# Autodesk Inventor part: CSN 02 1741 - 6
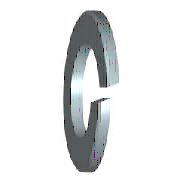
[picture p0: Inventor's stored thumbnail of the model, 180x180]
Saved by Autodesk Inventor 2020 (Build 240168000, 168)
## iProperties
Created: 2019-01
Part Number: CSN 02 1741 - 6
Material: Ocel, měkká
Description: Pružné podložky obdélníkového průřezu
Document SubType Name: Modeling
Standard: CSN 02 1741
Designer: doma
Standards Organization: CSN
Language: cs-CZ
Size Designation: 6
Categories: <MemberInstance><Categories><Category DisplayName="Spojovací materiál" InternalName="e4da775c-781d-43d5-af7c-5136215cf5a6" Mnemonic="FSTN"><Category DisplayName
Density: 7.85 g/cm^3
Appearance: Pololeštěná
IsCustomPart: 0
Author: doma
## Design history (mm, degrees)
sketch "Náčrt1"
  geometry: C1 r 5.55 at (0, 0); C2 r 3.05 at (0, 0); 1 further point
  constraints: 2 centre point, 2 coincident
  dimensions: "d0" = 6.1 diameter of C2 (= SD1); "d1" = 11.1 diameter of C1 (= SD2)
extrude "Těleso" new body sketch "Náčrt1" distance "d2" = 1.6 (= SD); taper "d3" = 0 deg
sketch "Náčrt2"
  geometry: L1 (0, -3.05)-(0, 3.05) reference; L2 (1.6, 5.55)-(1.6, -5.55) reference; L3 (-1.2, 0)-(7.2, 0) reference; L4 (0, -0.32)-(1.6, -0.038); L5 (0, 0.32)-(1.6, 0.602)
  constraints: 4 end point, 4 point on line, 1 parallel
  dimensions: "d4" = 0.32 distance from line of L3 L4.start (= 0.2 x SD); "d5" = 0.32 distance from line of L3 L5.start (= 0.2 x SD); "d6" = 80 deg angle of L2 L4 (= FAWI)
extrude "Výřez" cut sketch "Náčrt2" stored distance "d7" = 1.6 (= SD); taper "d8" = 0 deg
workaxis "Work Axis1"
workplane "Work Plane1"
body "Solid1"
other parameters: "SD1" = 6.1 [user parameter; used in 1 equation term], "SD2" = 11.1 [user parameter; used in 1 equation term], "SD" = 1.6 [user parameter; used in 4 equation terms], "FAWI" = 80 deg [user parameter; used in 1 equation term], "d9" = 0, "d10" = 0, "d11" = 0, "d12" = 0, "NND" = 6 [user parameter]
